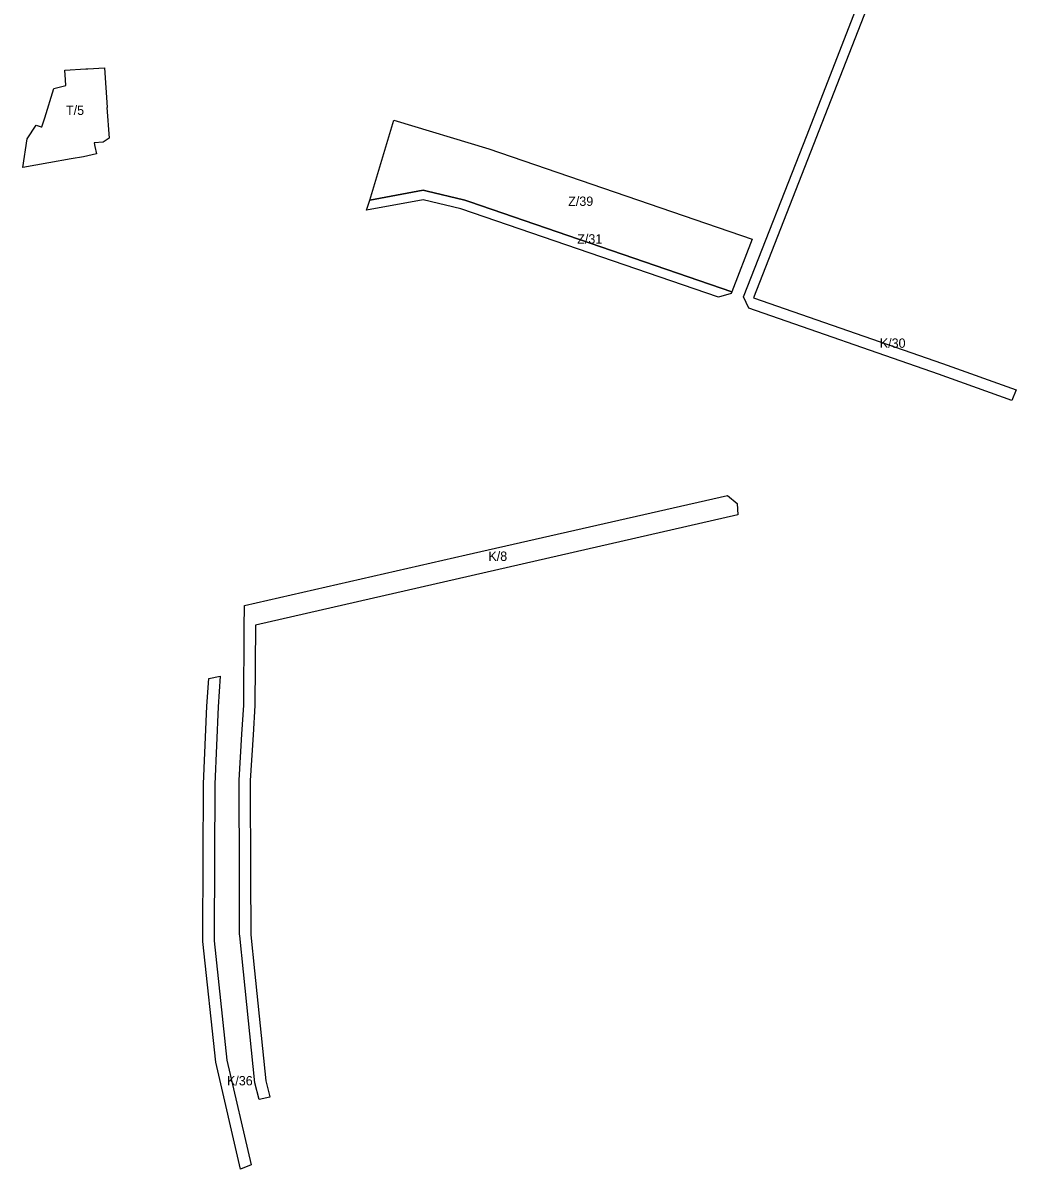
# Model space of a CAD drawing. Extents: x -521969 to -519862, y -1142171 to -1140238.
# Drawn here: x -520393 to -519862, y -1141720 to -1141108 of the extents above; entities that cross this region are included whole.
import ezdxf

# ---------------------------------------------------------------- set-up
doc = ezdxf.new("R2010")
doc.units = 0
for name, color, linetype in [('95420023', 7, 'Continuous'), ('96110023', 7, 'Continuous'), ('96111023', 7, 'Continuous')]:
    doc.layers.add(name, color=color, linetype=linetype)

msp = doc.modelspace()

# ---------------------------------------------------------------- linework, layer by layer
at = {"layer": '95420023'}
for points in [[(-520194.38, -1141159.65), (-520143.75, -1141175.06), (-520002.99, -1141223.35), (-520013.82, -1141251.35), (-520153.86, -1141203.31), (-520156.44, -1141202.42), (-520157.17, -1141202.17), (-520176.64, -1141197.6), (-520178.73, -1141197.11), (-520207.36, -1141202.47)], [(-520209, -1141207.86), (-520207.36, -1141202.47), (-520178.73, -1141197.11), (-520176.64, -1141197.6), (-520157.17, -1141202.17), (-520156.44, -1141202.42), (-520153.86, -1141203.31), (-520013.82, -1141251.35), (-520014.17, -1141252.24), (-520020.92, -1141254.2), (-520158.56, -1141206.98), (-520178.85, -1141202.22)]]:
    msp.add_lwpolyline(points, close=True, dxfattribs=at)
at = {"layer": '96110023'}
msp.add_lwpolyline([(-520392.71, -1141184.99), (-520390.51, -1141169.6), (-520385.67, -1141162.39), (-520383.02, -1141163.15), (-520382.54, -1141163.3), (-520381.05, -1141158.47), (-520376.18, -1141142.7), (-520369.8, -1141141.08), (-520369.99, -1141138.16), (-520370.32, -1141133), (-520359.15, -1141132.28), (-520357.95, -1141132.21), (-520349.11, -1141131.64), (-520347.61, -1141152.91), (-520347.81, -1141152.92), (-520346.65, -1141169.3), (-520349.86, -1141171.48), (-520354.71, -1141171.83), (-520354.34, -1141173.71), (-520353.47, -1141177.71), (-520360.34, -1141179.18), (-520366.93, -1141180.34), (-520378.86, -1141182.41)], close=True, dxfattribs=at)
at = {"layer": '96111023'}
for points in [[(-519942.77, -1141088.03), (-519941.9, -1141085.78), (-519941.89, -1141085.78), (-519935.26, -1141083.16), (-520002.16, -1141254.73), (-519901.27, -1141289.8), (-519861.86, -1141303.89), (-519864.09, -1141309.46), (-519903.26, -1141295.46), (-520004.78, -1141260.17), (-520007.53, -1141254.06), (-519973.57, -1141167.53)], [(-520277.2, -1141512.43), (-520275.67, -1141487.93), (-520274.69, -1141472.35), (-520274.48, -1141431.01), (-520274.28, -1141419.2), (-520155.8, -1141392.1), (-520016.19, -1141360.33), (-520010.91, -1141364.55), (-520010.61, -1141370.65), (-520268.47, -1141429.64), (-520268.69, -1141472.55), (-520269.68, -1141488.31), (-520271.2, -1141512.61), (-520271.03, -1141563.69), (-520270.93, -1141594.41), (-520270.85, -1141595.16), (-520268.87, -1141614.33), (-520262.8, -1141673.2), (-520260.68, -1141681.85), (-520260.66, -1141681.95), (-520266.52, -1141683.24), (-520268.73, -1141674.23), (-520274.84, -1141614.95), (-520276.82, -1141595.78), (-520276.93, -1141594.74), (-520277.03, -1141563.71)], [(-520276.36, -1141720.39), (-520289.6, -1141663.22), (-520296.53, -1141598.74), (-520296.52, -1141595.69), (-520296.19, -1141514.43), (-520294.41, -1141472.89), (-520293.35, -1141458.14), (-520287.25, -1141456.97), (-520288.42, -1141473.23), (-520290.19, -1141514.57), (-520290.52, -1141595.71), (-520290.53, -1141598.43), (-520283.67, -1141662.22), (-520270.75, -1141718.04)]]:
    msp.add_lwpolyline(points, close=True, dxfattribs=at)

# ---------------------------------------------------------------- texts
at = {"layer": '95420023'}
for s, rotation, p in [('Z/39', 0, (-520101.25, -1141205.5)), ('Z/31', 360, (-520096.42, -1141225.65))]:
    msp.add_text(s, height=5, rotation=rotation, dxfattribs=at).set_placement(p)
at = {"layer": '96110023'}
msp.add_text('T/5', height=5, rotation=0, dxfattribs=at).set_placement((-520369.68, -1141156.89))
at = {"layer": '96111023'}
for s, rotation, p in [('K/30', 0, (-519934.7, -1141281.36)), ('K/8', 0, (-520143.91, -1141395.27)), ('K/36', 360, (-520283.64, -1141675.65))]:
    msp.add_text(s, height=5, rotation=rotation, dxfattribs=at).set_placement(p)

doc.saveas('drawing.dxf')
